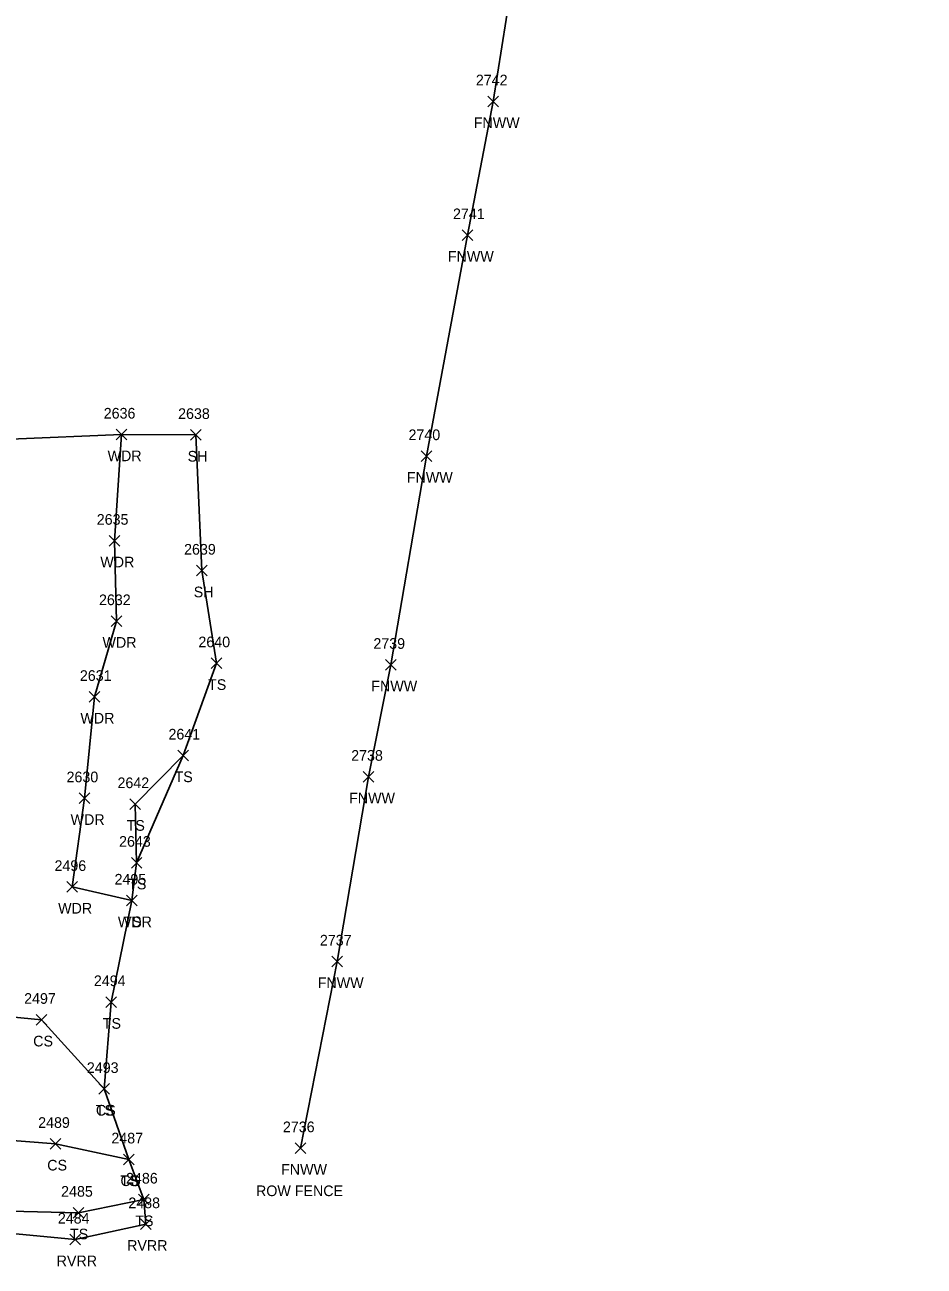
# Model space of a CAD drawing. Extents: x 1472022 to 1479249, y 777216 to 786527.
# Drawn here: x 1473823.2 to 1473992, y 779651.8 to 779884.8 of the extents above; entities that cross this region are included whole.
import ezdxf

# ---------------------------------------------------------------- set-up
doc = ezdxf.new("R2010")
doc.units = 0
for name, color, linetype in [('L_A', 7, 'Continuous'), ('L_C', 7, 'Continuous'), ('L_I', 7, 'Continuous'), ('L_TIC', 7, 'Continuous'), ('LAWA', 7, 'Continuous'), ('LAWE', 7, 'Continuous'), ('LELB', 7, 'Continuous'), ('LFNC', 7, 'Continuous'), ('LSOGP', 7, 'Continuous')]:
    doc.layers.add(name, color=color, linetype=linetype)

msp = doc.modelspace()

# ---------------------------------------------------------------- linework, layer by layer
at = {"layer": 'L_TIC'}
for points in [[(1473910.16, 779869.48), (1473912.16, 779871.48)], [(1473912.16, 779869.48), (1473910.16, 779871.48)], [(1473905.31, 779844.37), (1473907.31, 779846.37)], [(1473907.31, 779844.37), (1473905.31, 779846.37)], [(1473840.42, 779806.94), (1473842.42, 779808.94)], [(1473842.42, 779806.94), (1473840.42, 779808.94)], [(1473854.32, 779806.87), (1473856.32, 779808.87)], [(1473856.32, 779806.87), (1473854.32, 779808.87)], [(1473897.61, 779802.9), (1473899.61, 779804.9)], [(1473899.61, 779802.9), (1473897.61, 779804.9)], [(1473839.06, 779787.01), (1473841.06, 779789.01)], [(1473841.06, 779787.01), (1473839.06, 779789.01)], [(1473855.46, 779781.4), (1473857.46, 779783.4)], [(1473857.46, 779781.4), (1473855.46, 779783.4)], [(1473839.47, 779771.92), (1473841.47, 779773.92)], [(1473841.47, 779771.92), (1473839.47, 779773.92)], [(1473858.23, 779764.01), (1473860.23, 779766.01)], [(1473860.23, 779764.01), (1473858.23, 779766.01)], [(1473890.94, 779763.72), (1473892.94, 779765.72)], [(1473892.94, 779763.72), (1473890.94, 779765.72)], [(1473835.32, 779757.7), (1473837.32, 779759.7)], [(1473837.32, 779757.7), (1473835.32, 779759.7)], [(1473851.95, 779746.7), (1473853.95, 779748.7)], [(1473853.95, 779746.7), (1473851.95, 779748.7)], [(1473886.76, 779742.71), (1473888.76, 779744.71)], [(1473888.76, 779742.71), (1473886.76, 779744.71)], [(1473833.47, 779738.67), (1473835.47, 779740.67)], [(1473835.47, 779738.67), (1473833.47, 779740.67)], [(1473842.95, 779737.57), (1473844.95, 779739.57)], [(1473844.95, 779737.57), (1473842.95, 779739.57)], [(1473843.24, 779726.57), (1473845.24, 779728.57)], [(1473845.24, 779726.57), (1473843.24, 779728.57)], [(1473831.13, 779722.02), (1473833.13, 779724.02)], [(1473833.13, 779722.02), (1473831.13, 779724.02)], [(1473842.35, 779719.47), (1473844.35, 779721.47)], [(1473844.35, 779719.47), (1473842.35, 779721.47)], [(1473842.35, 779719.47), (1473844.35, 779721.47)], [(1473844.35, 779719.47), (1473842.35, 779721.47)], [(1473880.89, 779708.03), (1473882.89, 779710.03)], [(1473882.89, 779708.03), (1473880.89, 779710.03)], [(1473838.47, 779700.41), (1473840.47, 779702.41)], [(1473840.47, 779700.41), (1473838.47, 779702.41)], [(1473825.38, 779697.09), (1473827.38, 779699.09)], [(1473827.38, 779697.09), (1473825.38, 779699.09)], [(1473837.15, 779684.11), (1473839.15, 779686.11)], [(1473839.15, 779684.11), (1473837.15, 779686.11)], [(1473837.15, 779684.11), (1473839.15, 779686.11)], [(1473839.15, 779684.11), (1473837.15, 779686.11)], [(1473828.02, 779673.8), (1473830.02, 779675.8)], [(1473830.02, 779673.8), (1473828.02, 779675.8)], [(1473874, 779672.99), (1473876, 779674.99)], [(1473876, 779672.99), (1473874, 779674.99)], [(1473841.75, 779670.88), (1473843.75, 779672.88)], [(1473843.75, 779670.88), (1473841.75, 779672.88)], [(1473841.75, 779670.88), (1473843.75, 779672.88)], [(1473843.75, 779670.88), (1473841.75, 779672.88)], [(1473844.57, 779663.35), (1473846.57, 779665.35)], [(1473846.57, 779663.35), (1473844.57, 779665.35)], [(1473832.32, 779660.88), (1473834.32, 779662.88)], [(1473834.32, 779660.88), (1473832.32, 779662.88)], [(1473844.94, 779658.73), (1473846.94, 779660.73)], [(1473846.94, 779658.73), (1473844.94, 779660.73)], [(1473831.71, 779655.84), (1473833.71, 779657.84)], [(1473833.71, 779655.84), (1473831.71, 779657.84)]]:
    msp.add_lwpolyline(points, dxfattribs=at)
at = {"layer": 'LAWA'}
msp.add_lwpolyline([(1473843.35, 779720.47), (1473832.13, 779723.02), (1473834.47, 779739.67), (1473836.32, 779758.7), (1473840.47, 779772.92), (1473840.06, 779788.01), (1473841.42, 779807.94)], dxfattribs=at)
at = {"layer": 'LAWE'}
msp.add_lwpolyline([(1473721.66, 779684.59), (1473726.19, 779679.53), (1473730.08, 779672.96), (1473743.89, 779669.74), (1473756.99, 779666.69), (1473766.52, 779665.42), (1473779.36, 779661.55), (1473796.16, 779658.44), (1473812.33, 779658.77), (1473832.71, 779656.84), (1473845.94, 779659.73)], dxfattribs=at)
at = {"layer": 'LELB'}
for points in [[(1473859.23, 779765.01), (1473852.95, 779747.7), (1473843.95, 779738.57), (1473844.24, 779727.57)], [(1473844.24, 779727.57), (1473843.35, 779720.47)], [(1473731.8, 779676.33), (1473743.79, 779672.74), (1473757.86, 779668.57), (1473767.48, 779668), (1473780.18, 779664.58), (1473797.83, 779661.81), (1473812.71, 779662.37), (1473833.32, 779661.88), (1473845.57, 779664.35), (1473842.75, 779671.88), (1473838.15, 779685.11), (1473839.47, 779701.41), (1473843.35, 779720.47)], [(1473838.15, 779685.11), (1473826.38, 779698.09), (1473816.02, 779699.11), (1473801.5, 779686.22), (1473782.09, 779686.58)], [(1473842.75, 779671.88), (1473829.02, 779674.8), (1473812.03, 779676.11)]]:
    msp.add_lwpolyline(points, dxfattribs=at)
at = {"layer": 'LFNC'}
msp.add_lwpolyline([(1473875, 779673.99), (1473881.89, 779709.03), (1473887.76, 779743.71), (1473891.94, 779764.72), (1473898.61, 779803.9), (1473906.31, 779845.37), (1473911.16, 779870.48), (1473916.84, 779906.43), (1473925.6, 779951.14), (1473930.24, 779976.05), (1473935.19, 780005.03), (1473942.64, 780045), (1473949.23, 780080.08), (1473954.8, 780117.32), (1473965.64, 780175.79), (1473975.53, 780227.06), (1473985.2, 780275.69), (1474013.15, 780426.76), (1474027.53, 780457.02), (1474055.53, 780518.26), (1474067.56, 780545.19), (1474081.74, 780575.7)], dxfattribs=at)
at = {"layer": 'LSOGP'}
msp.add_lwpolyline([(1473812.33, 779658.77), (1473832.71, 779656.84), (1473845.94, 779659.73), (1473845.57, 779664.35), (1473842.75, 779671.88), (1473838.15, 779685.11), (1473839.47, 779701.41), (1473843.35, 779720.47), (1473844.24, 779727.57), (1473852.95, 779747.7), (1473859.23, 779765.01), (1473856.46, 779782.4), (1473855.32, 779807.87), (1473841.42, 779807.94), (1473820.59, 779807.07)], dxfattribs=at)

# ---------------------------------------------------------------- texts
at = {"layer": 'L_A'}
for s, p in [('FNWW', (1473907.51, 779865.48)), ('FNWW', (1473902.65, 779840.37)), ('WDR', (1473838.78, 779802.94)), ('SH', (1473853.81, 779802.87)), ('FNWW', (1473894.95, 779798.9)), ('WDR', (1473837.42, 779783.01)), ('SH', (1473854.95, 779777.4)), ('WDR', (1473837.83, 779767.92)), ('TS', (1473857.64, 779760.01)), ('FNWW', (1473888.28, 779759.72)), ('WDR', (1473833.68, 779753.7)), ('TS', (1473851.35, 779742.7)), ('FNWW', (1473884.11, 779738.71)), ('WDR', (1473831.84, 779734.67)), ('TS', (1473842.36, 779733.57)), ('TS', (1473842.65, 779722.57)), ('WDR', (1473829.5, 779718.02)), ('TS', (1473841.76, 779715.47)), ('WDR', (1473840.71, 779715.47)), ('FNWW', (1473878.23, 779704.03)), ('TS', (1473837.88, 779696.41)), ('CS', (1473824.82, 779693.09)), ('TS', (1473836.56, 779680.11)), ('CS', (1473836.59, 779680.11)), ('CS', (1473827.46, 779669.8)), ('FNWW', (1473871.35, 779668.99)), ('TS', (1473841.16, 779666.88)), ('CS', (1473841.19, 779666.88)), ('TS', (1473843.98, 779659.35)), ('TS', (1473831.73, 779656.88)), ('RVRR', (1473842.45, 779654.73)), ('RVRR', (1473829.22, 779651.84))]:
    msp.add_text(s, height=2, dxfattribs=at).set_placement(p)
at = {"layer": 'L_C'}
msp.add_text('ROW FENCE', height=2, dxfattribs=at).set_placement((1473866.64, 779664.99))
at = {"layer": 'L_I'}
for s, p in [('2742', (1473907.9, 779873.48)), ('2741', (1473903.61, 779848.37)), ('2636', (1473838.06, 779810.94)), ('2638', (1473852.02, 779810.87)), ('2740', (1473895.26, 779806.9)), ('2635', (1473836.75, 779791.01)), ('2639', (1473853.14, 779785.4)), ('2632', (1473837.17, 779775.92)), ('2640', (1473855.83, 779768.01)), ('2739', (1473888.67, 779767.72)), ('2631', (1473833.58, 779761.7)), ('2641', (1473850.21, 779750.7)), ('2738', (1473884.5, 779746.71)), ('2630', (1473831.08, 779742.67)), ('2642', (1473840.64, 779741.57)), ('2643', (1473840.94, 779730.57)), ('2496', (1473828.82, 779726.02)), ('2495', (1473840.09, 779723.47)), ('2495', (1473840.09, 779723.47)), ('2737', (1473878.63, 779712.03)), ('2494', (1473836.21, 779704.41)), ('2497', (1473823.12, 779701.09)), ('2493', (1473834.89, 779688.11)), ('2493', (1473834.89, 779688.11)), ('2489', (1473825.75, 779677.8)), ('2736', (1473871.69, 779676.99)), ('2487', (1473839.49, 779674.88)), ('2487', (1473839.49, 779674.88)), ('2486', (1473842.25, 779667.35)), ('2485', (1473830.06, 779664.88)), ('2488', (1473842.68, 779662.73)), ('2484', (1473829.45, 779659.84))]:
    msp.add_text(s, height=2, dxfattribs=at).set_placement(p)

doc.saveas('drawing.dxf')
